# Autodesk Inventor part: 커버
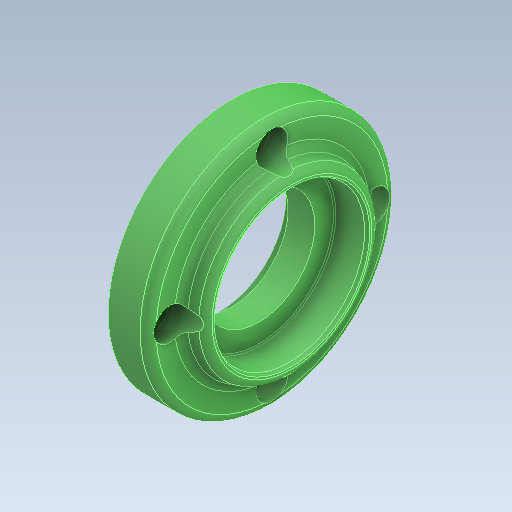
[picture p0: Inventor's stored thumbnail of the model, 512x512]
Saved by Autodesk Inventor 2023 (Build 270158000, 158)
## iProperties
Created: 2025-03
Part Number: 커버
Material: 알루미늄 6061
Document SubType Name: Modeling
Designer: Admin
Density: 2.71 g/cm^3
Appearance: 기본값
Author: jhkim
Sending System: Autodesk Inventor 2025
Preprocessor: ST-DEVELOPER v20
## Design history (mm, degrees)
feature "솔리드1"
node "솔리드2"
